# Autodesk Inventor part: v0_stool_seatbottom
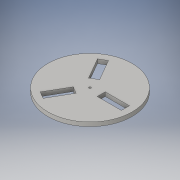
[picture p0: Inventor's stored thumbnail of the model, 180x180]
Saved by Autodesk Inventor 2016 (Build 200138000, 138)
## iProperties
Created: 2015-07
Part Number: v0_stool_seatbottom
Material: Generic
Document SubType Name: Modeling
Designer: t_patrw
Density: 1 g/cm^3
Appearance: Default
Author: t_patrw
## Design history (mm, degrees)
sketch "Sketch1"
  geometry: C1 r 190.5 at (0, 0); 1 further point
  constraints: 1 centre point, 1 coincident
  dimensions: "d0" = 381 diameter of C1 (= Seat_Diameter)
extrude "Extrusion1" new body sketch "Sketch1" distance "d1" = 18.288 (= Thickness); taper "d2" = 0 deg
sketch "Sketch2"
  geometry: C1 r 4.699 at (0, 0); 1 further point
  constraints: 1 centre point, 1 coincident
  dimensions: "d3" = 9.398 diameter of C1
extrude "Extrusion2" cut sketch "Sketch2" distance "d4" = 18.288 (= Thickness); taper "d5" = 0 deg
sketch "Sketch3"
  geometry: L1 (190.5, 0)-(0, 0); L2 (160.528, -18.288)-(50.8, -18.288); L3 (160.528, 18.288)-(50.8, 18.288); L4 (50.8, -18.288)-(50.8, 18.288); L5 (160.528, 18.288)-(160.528, -18.288); L6 (-95.25, 164.978)-(0, 0); L7 (-64.426, 148.165)-(-9.562, 53.138); L8 (-96.102, 129.877)-(-41.238, 34.85); L9 (-9.562, 53.138)-(-41.238, 34.85); L10 (-96.102, 129.877)-(-64.426, 148.165); L11 (-95.25, -164.978)-(0, 0); L12 (-96.102, -129.877)-(-41.238, -34.85); L13 (-64.426, -148.165)-(-9.562, -53.138); L14 (-41.238, -34.85)-(-9.562, -53.138); L15 (-64.426, -148.165)-(-96.102, -129.877); 2 further points
  constraints: 30 end point, 1 coincident, 1 horizontal, 1 horizontal alignment, 1 perpendicular, 1 vertical, 35 other
  dimensions: "d7" = 18.288 distance between parallel lines of L1 L2 (= Thickness); "d8" = 18.288 distance between parallel lines of L1 L3 (= Thickness); "d11" = 360 deg dimension on point (0, 0) L1.start (derived); "d15" = 160.528 distance from line of L5 point (0, 0) (computed from Thickness); "d16" = 50.8 distance from line of point (0, 0) L4
extrude "Extrusion3" cut sketch "Sketch3" distance "d13" = 18.288 (= Thickness); taper "d14" = 0 deg
body "Solid1"
other parameters: "Thickness" = 18.288 [user parameter; used in 6 equation terms], "Height" = 457.2 [user parameter], "Seat_Diameter" = 381 [user parameter; used in 1 equation term]
